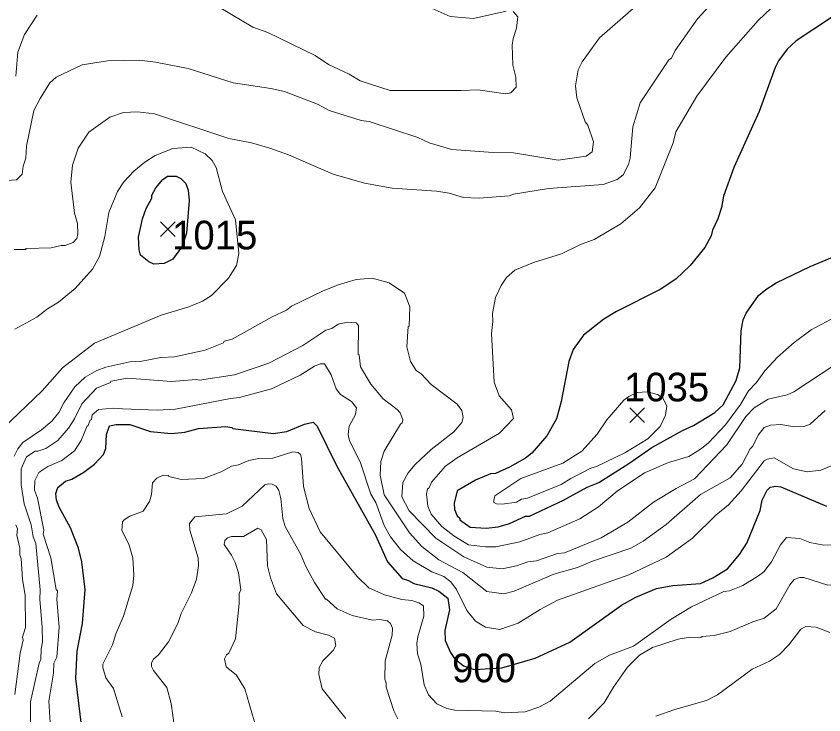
# Model space of a CAD drawing. Extents: x 265.7 to 292.1, y 7676.2 to 7704.2.
# Drawn here: x 284.439 to 286.697, y 7686.96 to 7688.913 of the extents above; entities that cross this region are included whole.
import ezdxf
from ezdxf.enums import TextEntityAlignment as Align

# ---------------------------------------------------------------- set-up
doc = ezdxf.new("R2010")
doc.units = 0
doc.header["$LTSCALE"] = 0.032
for name, color, linetype, lineweight in [('1', 7, 'Continuous', 25), ('2', 7, 'Continuous', 13), ('21', 7, 'Continuous', 25)]:
    doc.layers.add(name, color=color, linetype=linetype, lineweight=lineweight)
doc.layers.add('61', color=7, linetype='Continuous')

msp = doc.modelspace()

# ---------------------------------------------------------------- linework, layer by layer
at = {"layer": '1'}
for points in [[(286.718, 7688.9094), (286.6199, 7688.8439), (286.5943, 7688.8208), (286.5704, 7688.7889), (286.5608, 7688.7697), (286.5161, 7688.6468), (286.4451, 7688.4904), (286.4164, 7688.4106), (286.4108, 7688.3787), (286.4004, 7688.3468), (286.3853, 7688.3149), (286.3821, 7688.2989), (286.3645, 7688.267), (286.323, 7688.2159), (286.2831, 7688.1784), (286.2393, 7688.1497), (286.1172, 7688.0874), (286.0821, 7688.0659), (286.0254, 7688.022), (285.9959, 7687.9813), (285.9839, 7687.9478), (285.9631, 7687.8361), (285.9496, 7687.7882), (285.9224, 7687.7403), (285.881, 7687.6917), (285.8634, 7687.6781), (285.8187, 7687.6526), (285.7796, 7687.635), (285.7653, 7687.6342)], [(285.6799, 7687.5105), (285.6799, 7687.5057), (285.7086, 7687.485), (285.7533, 7687.4818), (285.7868, 7687.4858), (285.8187, 7687.4954), (285.8634, 7687.5153), (285.8746, 7687.5161), (285.9695, 7687.5608), (286.0358, 7687.5967), (286.0677, 7687.6095), (286.1523, 7687.6629), (286.2161, 7687.7076), (286.3023, 7687.7555), (286.3326, 7687.7691), (286.3925, 7687.8058), (286.4156, 7687.8273), (286.4523, 7687.8952), (286.4619, 7687.9303), (286.4659, 7688.034), (286.4715, 7688.0643), (286.4794, 7688.0835), (286.5145, 7688.1329), (286.5345, 7688.1497), (286.564, 7688.168), (286.659, 7688.2135), (286.7547, 7688.2534)], [(284.6266, 7686.8929), (284.6058, 7687.0621), (284.6098, 7687.1387), (284.625, 7687.2153), (284.6321, 7687.311), (284.6226, 7687.3876), (284.6138, 7687.426), (284.5915, 7687.4834), (284.5595, 7687.5409), (284.5524, 7687.56), (284.55, 7687.5792), (284.5555, 7687.5959), (284.5771, 7687.6135), (284.5947, 7687.619), (284.6282, 7687.6382), (284.6585, 7687.6613), (284.684, 7687.6885), (284.6904, 7687.7052), (284.692, 7687.7435), (284.7, 7687.7683), (284.7191, 7687.7722), (284.7574, 7687.7715), (284.8149, 7687.7523), (284.8723, 7687.7467), (284.9106, 7687.7507), (284.949, 7687.7611), (285.0256, 7687.7667), (285.0423, 7687.7635), (285.0447, 7687.7603), (285.158, 7687.7467), (285.1963, 7687.7523), (285.2458, 7687.773), (285.2697, 7687.7786), (285.2809, 7687.7675), (285.3359, 7687.6558), (285.4429, 7687.4643), (285.4772, 7687.3876), (285.5187, 7687.3414), (285.5362, 7687.3358), (285.5506, 7687.327), (285.6017, 7687.3158), (285.6208, 7687.3062), (285.6464, 7687.2863), (285.6503, 7687.2536), (285.6376, 7687.1961), (285.6384, 7687.1682), (285.6535, 7687.1347), (285.6649, 7687.1177), (285.6894, 7687.0969), (285.7196, 7687.0875), (285.7969, 7687.0913), (285.8905, 7687.1187), (285.9871, 7687.1634), (286.1315, 7687.2671), (286.1714, 7687.2895), (286.2289, 7687.3134), (286.2752, 7687.3214), (286.3526, 7687.3278), (286.3869, 7687.3429), (286.4276, 7687.3685), (286.4611, 7687.4084), (286.4818, 7687.4403), (286.5193, 7687.5313)], [(285.7653, 7687.6342), (285.723, 7687.6166), (285.6719, 7687.5863), (285.6639, 7687.552), (285.6647, 7687.5345), (285.6719, 7687.5169), (285.6799, 7687.5105)], [(286.5193, 7687.5313), (286.5249, 7687.56), (286.5385, 7687.5887), (286.5465, 7687.5967), (286.5624, 7687.5999), (286.5768, 7687.5975), (286.7045, 7687.5432)]]:
    msp.add_lwpolyline(points, dxfattribs=at)
msp.add_lwpolyline([(284.9155, 7688.3066), (284.9034, 7688.2703), (284.8771, 7688.2343), (284.8532, 7688.2215), (284.8245, 7688.2199), (284.8101, 7688.2263), (284.787, 7688.2454), (284.783, 7688.2606), (284.7814, 7688.2957), (284.7925, 7688.3468), (284.8029, 7688.3755), (284.8189, 7688.4043), (284.8189, 7688.413), (284.83, 7688.433), (284.8492, 7688.4569), (284.862, 7688.4657), (284.8867, 7688.4665), (284.8995, 7688.4593), (284.9138, 7688.4457), (284.9202, 7688.4266), (284.9234, 7688.3979)], close=True, dxfattribs=at)
at = {"layer": '2'}
for points in [[(285.7708, 7688.0819), (285.7788, 7688.1266), (285.7948, 7688.1601), (285.8099, 7688.1824), (285.8331, 7688.2032), (285.8858, 7688.2247), (285.964, 7688.2494), (286.015, 7688.2742), (286.0549, 7688.2893), (286.1299, 7688.3332), (286.1818, 7688.3771), (286.2257, 7688.433), (286.276, 7688.5591), (286.2831, 7688.5902), (286.3422, 7688.6899), (286.4228, 7688.7984), (286.5129, 7688.9014), (286.5497, 7688.9357), (286.5943, 7688.966), (286.6358, 7688.9828), (286.6566, 7688.9876), (286.7053, 7689.0131)], [(286.4164, 7688.986), (286.3438, 7688.9054), (286.2815, 7688.8176), (286.2712, 7688.796), (286.264, 7688.7913), (286.1834, 7688.6708), (286.1634, 7688.6037), (286.1555, 7688.5176), (286.1507, 7688.4984), (286.1363, 7688.4697), (286.1188, 7688.4569), (286.0805, 7688.4425), (285.9273, 7688.4314), (285.8291, 7688.4162), (285.8171, 7688.4114), (285.7333, 7688.4042), (285.6895, 7688.4066), (285.6496, 7688.4186), (285.6145, 7688.4242), (285.49, 7688.4322), (285.4134, 7688.4465), (285.3256, 7688.4713), (285.2003, 7688.5255), (285.1484, 7688.5447), (285.0974, 7688.559), (285.0335, 7688.571), (284.8261, 7688.6404), (284.7782, 7688.646), (284.7399, 7688.6436), (284.7016, 7688.6309), (284.6425, 7688.5894), (284.613, 7688.5447), (284.597, 7688.4968), (284.5923, 7688.4489), (284.6026, 7688.3628), (284.6106, 7688.334), (284.6122, 7688.3053), (284.609, 7688.2917), (284.5986, 7688.2806), (284.5763, 7688.2718), (284.5651, 7688.2726), (284.5372, 7688.2654), (284.4678, 7688.2638), (284.4654, 7688.2614), (284.4335, 7688.2614)], [(286.2073, 7688.974), (286.0701, 7688.8527), (286.0214, 7688.7857), (286.0102, 7688.7633), (286.0031, 7688.7186), (286.0062, 7688.6851), (286.0302, 7688.6181), (286.0374, 7688.6085), (286.0533, 7688.5622), (286.0493, 7688.5343), (286.0326, 7688.5223), (285.9544, 7688.5112), (285.8299, 7688.5311), (285.7724, 7688.5319), (285.6575, 7688.5407), (285.5937, 7688.559), (285.5618, 7688.5742), (285.4261, 7688.6189), (285.4038, 7688.6221), (285.3144, 7688.65), (285.2817, 7688.6676), (285.1899, 7688.7027), (285.1516, 7688.7115), (285.0463, 7688.7274), (284.9202, 7688.7673), (284.8293, 7688.7849), (284.7846, 7688.7905), (284.6952, 7688.7889)], [(285.8283, 7688.9261), (285.8419, 7688.911), (285.8379, 7688.8798), (285.8283, 7688.8511), (285.8259, 7688.832), (285.8275, 7688.7761), (285.8363, 7688.7426), (285.8371, 7688.7147), (285.8219, 7688.6987), (285.8076, 7688.6963), (285.731, 7688.7075), (285.6831, 7688.7051), (285.4844, 7688.7059), (285.4006, 7688.733), (285.3703, 7688.7514), (285.3128, 7688.7785), (285.2753, 7688.8032), (285.1429, 7688.8679), (285.1006, 7688.883), (285.0064, 7688.9381)], [(285.5857, 7688.9421), (285.6528, 7688.9125), (285.7174, 7688.907), (285.8092, 7688.9269)], [(284.4981, 7688.9157), (284.463, 7688.8623), (284.4446, 7688.8128), (284.4382, 7688.7458)], [(284.6952, 7688.7889), (284.6242, 7688.7769), (284.5516, 7688.7426), (284.534, 7688.7274), (284.5061, 7688.6835), (284.4893, 7688.65), (284.4686, 7688.5495)], [(284.4359, 7688.0388), (284.4973, 7688.0723), (284.5268, 7688.0954), (284.558, 7688.1138), (284.6042, 7688.1521), (284.6529, 7688.2064), (284.6728, 7688.2415), (284.6872, 7688.2973), (284.6984, 7688.3644), (284.7231, 7688.4234), (284.7407, 7688.4505), (284.7686, 7688.4801), (284.7989, 7688.5056), (284.8277, 7688.5239), (284.8771, 7688.5431), (284.929, 7688.5471), (284.9681, 7688.5287), (284.9872, 7688.5096), (284.9984, 7688.4904), (285.016, 7688.4234), (285.0525, 7688.3439), (285.0616, 7688.2498), (285.0551, 7688.2159), (285.0327, 7688.1808), (284.9857, 7688.1329), (284.9601, 7688.117), (284.9218, 7688.101), (284.8452, 7688.0779), (284.6585, 7687.9989), (284.5691, 7687.9303), (284.5125, 7687.8656), (284.4031, 7687.7619)], [(284.4686, 7688.5495), (284.4662, 7688.516), (284.459, 7688.4936), (284.4558, 7688.4721), (284.4406, 7688.4561), (284.4127, 7688.4537)], [(284.4335, 7687.6837), (284.4438, 7687.7036), (284.4582, 7687.722), (284.5101, 7687.7571), (284.5388, 7687.781), (284.5587, 7687.8058), (284.5731, 7687.8329), (284.6034, 7687.8768), (284.6322, 7687.9039), (284.6649, 7687.9231), (284.6904, 7687.9326), (284.7574, 7687.947), (284.7862, 7687.9478), (284.8436, 7687.959), (284.8819, 7687.9614), (284.9681, 7687.9797), (285.0192, 7688.0005), (285.0208, 7688.0045), (285.0431, 7688.0108), (285.1548, 7688.0731), (285.1947, 7688.0914), (285.2091, 7688.1026), (285.2953, 7688.1449), (285.3392, 7688.1625), (285.3894, 7688.1768), (285.4341, 7688.1808), (285.482, 7688.168), (285.5251, 7688.1393), (285.5402, 7688.101), (285.5378, 7688.0468), (285.5354, 7688.046), (285.5315, 7687.9893), (285.5418, 7687.9478), (285.5578, 7687.9231), (285.5714, 7687.9135), (285.5993, 7687.884), (285.6719, 7687.8289), (285.6847, 7687.8106), (285.6887, 7687.7914), (285.6855, 7687.7778), (285.6631, 7687.7515), (285.5993, 7687.702), (285.5546, 7687.6598), (285.5354, 7687.6366), (285.5203, 7687.6095), (285.5171, 7687.5696), (285.5378, 7687.5305), (285.6121, 7687.4539), (285.6911, 7687.402), (285.7549, 7687.3733), (285.798, 7687.3685), (285.8379, 7687.3765), (285.8698, 7687.3876), (285.8937, 7687.3908), (285.9528, 7687.4116), (285.9719, 7687.4132), (286.0741, 7687.4547), (286.1491, 7687.4986), (286.2209, 7687.5544), (286.2839, 7687.5927), (286.3358, 7687.6198), (286.426, 7687.7148), (286.4786, 7687.7946)], [(286.7172, 7688.0659), (286.6614, 7688.0364), (286.6135, 7688.0013), (286.5672, 7687.9598), (286.5321, 7687.9223), (286.5074, 7687.888), (286.4866, 7687.8656), (286.4635, 7687.8281), (286.422, 7687.7707), (286.3741, 7687.7204), (286.355, 7687.7044), (286.3198, 7687.6829), (286.2624, 7687.6653), (286.1954, 7687.6366), (286.1196, 7687.5855), (286.0669, 7687.5416), (286.015, 7687.5081), (285.9257, 7687.469), (285.9033, 7687.4642), (285.8475, 7687.4443), (285.7804, 7687.4299), (285.7517, 7687.4299), (285.7038, 7687.4355), (285.6623, 7687.4603), (285.6296, 7687.4866), (285.5993, 7687.5217), (285.5897, 7687.544), (285.5865, 7687.5776), (285.5889, 7687.5919), (285.5937, 7687.5951), (285.6001, 7687.6111), (285.6392, 7687.6558), (285.6719, 7687.6789), (285.79, 7687.7475), (285.8291, 7687.789)], [(285.8291, 7687.789), (285.8235, 7687.813), (285.7892, 7687.8521), (285.7756, 7687.8904), (285.7677, 7688.026), (285.7716, 7688.0595), (285.7708, 7688.0819)], [(285.0495, 7687.9111), (285.1453, 7687.9438), (285.241, 7687.9925), (285.3048, 7688.0356), (285.3216, 7688.0404), (285.3399, 7688.0523), (285.3655, 7688.0579)], [(285.3655, 7688.0579), (285.3902, 7688.0563), (285.3966, 7688.0491), (285.395, 7687.9678), (285.3982, 7687.9662), (285.4022, 7687.9335), (285.4309, 7687.8848), (285.4652, 7687.8441), (285.5043, 7687.8138), (285.5123, 7687.8042), (285.5203, 7687.785), (285.5187, 7687.7763), (285.5139, 7687.7731), (285.4676, 7687.6973), (285.4588, 7687.6685), (285.4572, 7687.6302), (285.4676, 7687.5752), (285.5386, 7687.469), (285.5729, 7687.4307), (285.6208, 7687.3932), (285.6879, 7687.3581), (285.7549, 7687.3047), (285.8028, 7687.2983), (285.8315, 7687.3062), (285.9424, 7687.3533), (286.0086, 7687.3725), (286.0501, 7687.39), (286.1571, 7687.4259), (286.1922, 7687.4459), (286.256, 7687.4922), (286.3526, 7687.576), (286.4348, 7687.623), (286.4683, 7687.6613), (286.4914, 7687.7036), (286.4986, 7687.7116), (286.5129, 7687.7419), (286.5297, 7687.7635), (286.5481, 7687.7699), (286.5768, 7687.7723), (286.6151, 7687.7651), (286.6406, 7687.7667), (286.659, 7687.7731), (286.7005, 7687.8106)], [(286.4786, 7687.7946), (286.5026, 7687.8185), (286.5417, 7687.8425), (286.5943, 7687.8552), (286.6127, 7687.8632), (286.7627, 7687.9622), (286.8018, 7687.9749)], [(284.7367, 7687.8161), (284.834, 7687.8122), (284.8851, 7687.8146), (285.0383, 7687.8449), (285.0639, 7687.8473), (285.1532, 7687.872), (285.233, 7687.9095), (285.2729, 7687.935), (285.2889, 7687.9414), (285.3008, 7687.9414), (285.32, 7687.9111), (285.3336, 7687.8712), (285.3463, 7687.856), (285.3767, 7687.8361), (285.391, 7687.8185), (285.3878, 7687.7994), (285.3703, 7687.7675), (285.3671, 7687.7435), (285.3711, 7687.726), (285.4006, 7687.6677), (285.4309, 7687.5776), (285.4445, 7687.5536), (285.4676, 7687.4898), (285.486, 7687.4579), (285.5139, 7687.4228), (285.549, 7687.3908), (285.6009, 7687.3597), (285.6344, 7687.3469), (285.6543, 7687.3318), (285.6703, 7687.311), (285.699, 7687.252), (285.723, 7687.2225), (285.7517, 7687.2057), (285.7916, 7687.1993), (285.8427, 7687.2169), (285.9041, 7687.2552), (285.9528, 7687.2807), (286.1523, 7687.3517), (286.256, 7687.4012), (286.3294, 7687.4539), (286.3949, 7687.5185), (286.43, 7687.5472), (286.4659, 7687.5863), (286.5297, 7687.6701), (286.5385, 7687.6749), (286.5584, 7687.6789), (286.6119, 7687.6478), (286.6502, 7687.6398), (286.6885, 7687.6438), (286.7172, 7687.6566)], [(284.4797, 7686.8961), (284.4797, 7686.9966), (284.5037, 7687.1052), (284.5085, 7687.1163), (284.5093, 7687.1451), (284.5133, 7687.1642), (284.5125, 7687.2057), (284.5053, 7687.2823), (284.5069, 7687.3094), (284.4941, 7687.4395), (284.4869, 7687.4579), (284.4813, 7687.4914), (284.4622, 7687.5504), (284.4534, 7687.6031), (284.4534, 7687.6478), (284.4686, 7687.6813), (284.4925, 7687.6972), (284.5005, 7687.6972), (284.5228, 7687.7052), (284.5564, 7687.7268), (284.5859, 7687.7619), (284.6026, 7687.7874), (284.6234, 7687.8297), (284.6641, 7687.8736), (284.7032, 7687.8896), (284.704, 7687.8928), (284.7511, 7687.9015), (284.8739, 7687.892), (284.9426, 7687.8975), (284.9521, 7687.8959), (285.0495, 7687.9111)], [(284.5364, 7686.9089), (284.5308, 7686.9982), (284.5436, 7687.0764), (284.5452, 7687.1044), (284.5532, 7687.1211), (284.5595, 7687.2057), (284.5532, 7687.2823), (284.5548, 7687.307), (284.5516, 7687.311), (284.5364, 7687.3988), (284.5149, 7687.4658), (284.5164, 7687.477), (284.4989, 7687.5664), (284.4909, 7687.5887), (284.4917, 7687.6151), (284.5029, 7687.6374), (284.5276, 7687.6542), (284.5667, 7687.6717), (284.6026, 7687.6981), (284.621, 7687.7269), (284.6378, 7687.7681), (284.6401, 7687.7675), (284.6465, 7687.7842), (284.6497, 7687.7858), (284.6521, 7687.7986), (284.6697, 7687.8138), (284.7128, 7687.8177), (284.7367, 7687.8161)], [(284.9633, 7687.6206), (285.0128, 7687.6398), (285.0415, 7687.6558), (285.0607, 7687.6589), (285.0894, 7687.6709), (285.1181, 7687.6765), (285.1564, 7687.6781), (285.2131, 7687.6957), (285.2274, 7687.6941), (285.2338, 7687.6885), (285.237, 7687.6781), (285.2426, 7687.5983), (285.2586, 7687.5369), (285.2889, 7687.4722), (285.3926, 7687.3469), (285.4253, 7687.3158), (285.4692, 7687.2959), (285.5171, 7687.2823), (285.5458, 7687.2799), (285.565, 7687.2735), (285.5777, 7687.2648), (285.5785, 7687.236), (285.5618, 7687.1786), (285.5594, 7687.1594), (285.561, 7687.1307), (285.5706, 7687.102), (285.5801, 7687.0445), (285.5921, 7687.0158), (285.6152, 7686.9911), (285.6432, 7686.9783), (285.6655, 7686.9735), (285.7804, 7686.9703), (285.8044, 7686.9663), (285.8618, 7686.9687), (285.9001, 7686.9815), (285.932, 7686.9982), (286.0565, 7687.1036), (286.098, 7687.1275), (286.165, 7687.1522), (286.2704, 7687.228), (286.327, 7687.2624), (286.4172, 7687.3047), (286.4332, 7687.307), (286.4707, 7687.3222), (286.5146, 7687.3485), (286.5289, 7687.3605), (286.5505, 7687.3876), (286.576, 7687.4355), (286.5928, 7687.4563), (286.6295, 7687.4531), (286.6582, 7687.4419), (286.6965, 7687.4347), (286.7492, 7687.4363)], [(284.8205, 7687.6087), (284.8324, 7687.6222), (284.85, 7687.6302), (284.8652, 7687.6294), (284.866, 7687.6262), (284.9011, 7687.6183), (284.9633, 7687.6206)], [(284.7359, 7686.9552), (284.7112, 7687.0341), (284.6904, 7687.0637), (284.6816, 7687.0924), (284.6816, 7687.102), (284.7088, 7687.1562), (284.7183, 7687.1866), (284.7399, 7687.236), (284.7654, 7687.3222), (284.7686, 7687.3509), (284.7654, 7687.3988), (284.7542, 7687.4371), (284.7351, 7687.4754), (284.7367, 7687.4994), (284.7415, 7687.5057), (284.7574, 7687.5153), (284.7941, 7687.5297), (284.8117, 7687.5568), (284.8181, 7687.576), (284.8205, 7687.6087)], [(284.8819, 7686.9248), (284.8731, 7686.9919), (284.8604, 7687.0365), (284.8229, 7687.0844), (284.8181, 7687.0956), (284.8181, 7687.106), (284.8229, 7687.1155), (284.8372, 7687.1283), (284.8652, 7687.1642), (284.8915, 7687.2153), (284.9011, 7687.244), (284.9298, 7687.3015), (284.9434, 7687.3398), (284.9489, 7687.3781), (284.9481, 7687.3988), (284.925, 7687.477), (284.9242, 7687.4954), (284.9386, 7687.5137), (285.0272, 7687.5225), (285.071, 7687.544), (285.1341, 7687.6031), (285.1437, 7687.6063), (285.1548, 7687.6055), (285.166, 7687.5991), (285.1732, 7687.5871), (285.1796, 7687.5648), (285.1851, 7687.5089), (285.1915, 7687.4866), (285.2354, 7687.4084), (285.249, 7687.3749), (285.2729, 7687.3302), (285.304, 7687.2839), (285.3072, 7687.2839), (285.3368, 7687.2568), (285.3783, 7687.2384), (285.4357, 7687.2249), (285.4549, 7687.2265), (285.4772, 7687.2233), (285.486, 7687.2153), (285.4916, 7687.2025), (285.4908, 7687.1834), (285.4708, 7687.1116), (285.47, 7687.0605), (285.474, 7687.0493), (285.4732, 7687.0381), (285.4955, 7686.9711), (285.5059, 7686.9488)], [(284.4359, 7687.0174), (284.451, 7687.1323), (284.459, 7687.169), (284.4574, 7687.177), (284.4654, 7687.2041), (284.4646, 7687.2935), (284.4574, 7687.3398), (284.4534, 7687.3972), (284.4494, 7687.4068), (284.4494, 7687.426), (284.4414, 7687.4627), (284.443, 7687.4802), (284.4382, 7687.4914)], [(285.1181, 7686.8993), (285.0782, 7687.0334), (285.0551, 7687.0709), (285.0263, 7687.0948), (285.0216, 7687.1171), (285.0271, 7687.1283), (285.0335, 7687.1331), (285.0527, 7687.173), (285.0631, 7687.2711), (285.0631, 7687.2999), (285.067, 7687.3094), (285.0607, 7687.3573), (285.0519, 7687.3861), (285.0415, 7687.4068), (285.0208, 7687.4363), (285.0224, 7687.4475), (285.0303, 7687.4547), (285.0415, 7687.4587), (285.075, 7687.4587), (285.1149, 7687.4818), (285.1245, 7687.4778), (285.1389, 7687.4507), (285.1421, 7687.3765), (285.15, 7687.343), (285.1668, 7687.2983), (285.2418, 7687.2105), (285.2761, 7687.1921), (285.3128, 7687.1834), (285.3296, 7687.1746), (285.3328, 7687.1546), (285.3256, 7687.1403), (285.2969, 7687.1115), (285.2865, 7687.0924), (285.2857, 7687.0733), (285.2945, 7687.0333), (285.3607, 7686.9504)], [(286.564, 7687.2568), (286.6023, 7687.3238), (286.6135, 7687.3382), (286.6295, 7687.3445), (286.6406, 7687.3438), (286.7077, 7687.323), (286.7555, 7687.3246)], [(286.039, 7686.9488), (286.0828, 7686.9935), (286.1092, 7687.0381), (286.1483, 7687.0932), (286.1818, 7687.1267), (286.2177, 7687.1483), (286.2895, 7687.1722), (286.323, 7687.177), (286.3534, 7687.1762), (286.3566, 7687.1794), (286.3901, 7687.1818), (286.4348, 7687.1929), (286.4986, 7687.2201), (286.5305, 7687.2304), (286.564, 7687.2568)], [(286.2273, 7686.9567), (286.28, 7686.9751), (286.3693, 7687.0006), (286.3996, 7687.0166), (286.497, 7687.0884), (286.5449, 7687.1107), (286.5728, 7687.1291), (286.5991, 7687.1562), (286.6326, 7687.2001), (286.647, 7687.2073), (286.6757, 7687.2057), (286.714, 7687.1905)]]:
    msp.add_lwpolyline(points, dxfattribs=at)
msp.add_lwpolyline([(286.1378, 7687.8395), (286.1516, 7687.8505), (286.1751, 7687.8616), (286.2027, 7687.8629), (286.2317, 7687.856), (286.2469, 7687.8464), (286.258, 7687.8229), (286.2544, 7687.7978), (286.2392, 7687.7659), (286.2049, 7687.7316), (286.1411, 7687.6925), (286.0613, 7687.6542), (286.0454, 7687.6494), (285.9895, 7687.6214), (285.9624, 7687.6039), (285.8682, 7687.5664), (285.8522, 7687.5632), (285.8379, 7687.5552), (285.798, 7687.5488), (285.782, 7687.5504), (285.774, 7687.5552), (285.7772, 7687.5728), (285.8498, 7687.6214), (285.9672, 7687.6637), (286.0206, 7687.6972), (286.0629, 7687.7451), (286.0908, 7687.785)], close=True, dxfattribs=at)
at = {"layer": '21'}
for p, q in [((284.8427, 7688.3387), (284.8839, 7688.2975)), ((284.8839, 7688.3387), (284.8427, 7688.2975)), ((286.1547, 7687.8184), (286.1959, 7687.7772)), ((286.1959, 7687.8184), (286.1547, 7687.7772))]:
    msp.add_line(p, q, dxfattribs=at)

# ---------------------------------------------------------------- texts
at = {"layer": '61'}
for s, p in [('1015', (284.9944, 7688.2614)), ('1035', (286.2574, 7687.8366)), ('900', (285.747, 7687.0514))]:
    msp.add_text(s, height=0.08, dxfattribs=at).set_placement(p, align=Align.CENTER)

doc.saveas('drawing.dxf')
